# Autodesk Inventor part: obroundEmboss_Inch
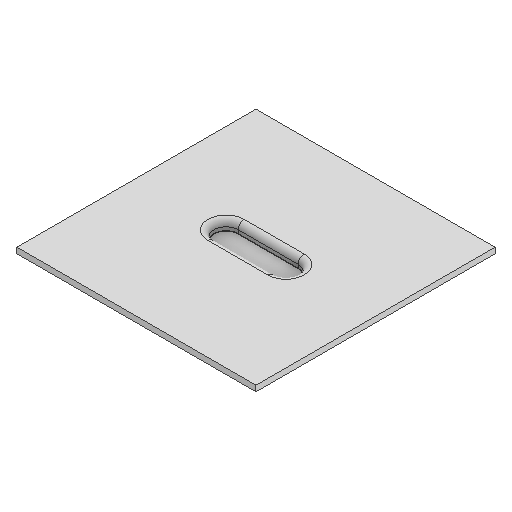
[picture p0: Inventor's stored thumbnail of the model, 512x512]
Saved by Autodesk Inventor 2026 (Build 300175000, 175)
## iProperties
Created: 2025-04
Part Number: obroundEmboss_Inch
Material: Generic
Document SubType Name: Sheet Metal
Designer: Autodesk, Inc
Density: 1 g/cm^3
Sheet Metal Rule: Default
Appearance: Default
Author: Autodesk, Inc
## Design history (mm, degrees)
node "Face1"
  sketch "Sketch1"
    geometry: L1 (-63.5, 63.5)-(63.5, 63.5); L2 (63.5, 63.5)-(63.5, -63.5); L3 (63.5, -63.5)-(-63.5, -63.5); L4 (-63.5, -63.5)-(-63.5, 63.5); L5 (-63.5, 63.5)-(63.5, -63.5); L6 (63.5, 63.5)-(-63.5, -63.5); 1 further point
    constraints: 12 end point, 2 midpoint, 2 parallel, 2 perpendicular, 1 horizontal
    dimensions: "d0" = 127 distance of L1.start L1.end
sketch "Sketch2"
  geometry: L1 (-15.875, 0)-(15.875, 0); L2 (-15.875, 9.525)-(15.875, 9.525); L3 (15.875, -9.525)-(-15.875, -9.525); L4 (-15.875, 0)-(15.875, 0); L5 (-15.875, 6.477)-(15.875, 6.477); L6 (15.875, -6.477)-(-15.875, -6.477); A1 r 9.525 centre (-15.875, 0) between (-15.875, 9.525) and (-15.875, -9.525); A2 r 9.525 centre (15.875, 0) between (15.875, -9.525) and (15.875, 9.525); A3 r 6.477 centre (-15.875, 0) between (-15.875, 6.477) and (-15.875, -6.477); A4 r 6.477 centre (15.875, 0) between (15.875, -6.477) and (15.875, 6.477); 8 further points
  constraints: 16 end point, 12 point on circle, 8 tangent, 4 centre point, 3 equal length, 2 coincident, 2 midpoint, 1 horizontal
  dimensions: "width" = 19.05 distance between parallel lines of L3 L2; "length" = 50.8 distance of point (25.4, 0) point (-25.4, 0); "d4" = 44.704 distance of point (22.352, 0) point (-22.352, 0) (= length - 2 x Thickness)
extrude "Extrusion1" join sketch "Sketch2" distance "d5" = 8.128 (= Thickness + depth); taper "d6" = 0 deg
extrude "Extrusion2" cut sketch "Sketch2" distance "d7" = 5.08 (= depth); taper "d8" = 0 deg
fillet "Fillet1" dims "d9" = 3.175 (= fillet_radius), "d10" = 0.127 (= fillet_radius - Thickness)
body "Solid1"
face "Plate1" dims "d1" = 3.048 (= Thickness)
other parameters: "Thickness" = 3.048, "BendRadius" = 3.048 (= Thickness), "BendReliefWidth" = 3.048 (= Thickness), "BendReliefDepth" = 1.524 (= 0.5 x Thickness), "CornerReliefSize" = 12.192 (= 4 x Thickness), "SeamGap" = 0.00508, "MinimumRemnant" = 6.096 (= 2 x Thickness), "TransitionRadius" = 3.048 (= BendRadius), "JacobiRadiusSize" = 3.048 (= BendRadius), "GapSize" = 3.048 (= Thickness), "depth" = 5.08 [user parameter; used in 2 equation terms], "fillet_radius" = 3.175 [user parameter; used in 2 equation terms]
